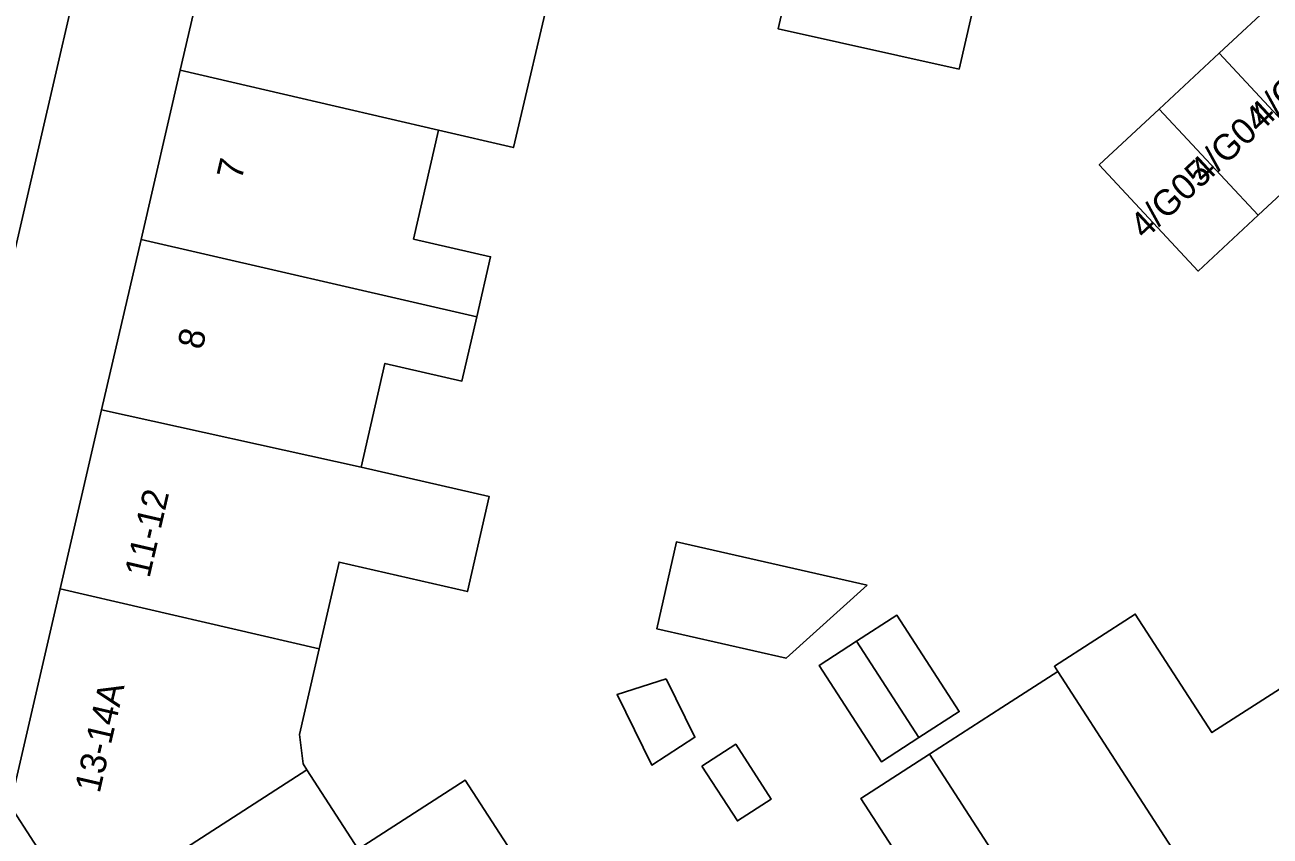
# Model space of a CAD drawing. Extents: x 161801 to 162379, y 382315 to 382832.
# Drawn here: x 161894.26 to 161942.5, y 382605.87 to 382637.32 of the extents above; entities that cross this region are included whole.
import ezdxf

# ---------------------------------------------------------------- set-up
doc = ezdxf.new("R2010")
doc.units = 0
for name, color, linetype in [('IMGEO_Pand', 7, 'Continuous'), ('IMGEO_Pand_nummerreeks', 7, 'Continuous'), ('IMGEO_Rijbaan_lokaal_open', 7, 'Continuous')]:
    doc.layers.add(name, color=color, linetype=linetype)

msp = doc.modelspace()

# ---------------------------------------------------------------- linework, layer by layer
at = {"layer": 'IMGEO_Pand'}
for points in [[(161927.536, 382642.861), (161924.886, 382643.471), (161923.437, 382637.168), (161930.448, 382635.605), (161931.888, 382641.86), (161927.536, 382642.861)], [(161900.274, 382635.56), (161901.764, 382642)], [(161914.727, 382639.11), (161913.18, 382632.56), (161910.284, 382633.233)], [(161940.52, 382636.218), (161942.842, 382638.382)], [(161938.199, 382634.054), (161940.52, 382636.218)], [(161940.52, 382636.218), (161944.36, 382632.099)], [(161898.755, 382628.994), (161900.274, 382635.56)], [(161910.284, 382633.233), (161900.274, 382635.56)], [(161942.038, 382629.935), (161939.717, 382627.771), (161935.877, 382631.89), (161938.199, 382634.054)], [(161942.038, 382629.935), (161938.199, 382634.054)], [(161910.284, 382633.233), (161909.313, 382629.014), (161912.296, 382628.327), (161911.761, 382626)], [(161944.36, 382632.099), (161942.038, 382629.935)], [(161897.228, 382622.395), (161898.755, 382628.994)], [(161911.761, 382626), (161898.755, 382628.994)], [(161911.761, 382626), (161911.187, 382623.507), (161908.202, 382624.194), (161907.278, 382620.174)], [(161895.622, 382615.453), (161897.228, 382622.395)], [(161897.228, 382622.395), (161907.278, 382620.174)], [(161907.278, 382620.174), (161912.245, 382619.032), (161911.397, 382615.348), (161906.428, 382616.491), (161905.656, 382613.133)], [(161926.892, 382615.591), (161923.748, 382612.762), (161918.733, 382613.907), (161919.497, 382617.271), (161926.892, 382615.591)], [(161896.429, 382602.791), (161893.679, 382607.053), (161895.622, 382615.453)], [(161895.622, 382615.453), (161905.656, 382613.133)], [(161928.891, 382609.687), (161930.453, 382610.696), (161928.041, 382614.428), (161926.479, 382613.419)], [(161934.272, 382612.252), (161934.142, 382612.454), (161937.273, 382614.477), (161940.244, 382609.881), (161943.037, 382611.685)], [(161905.656, 382613.133), (161904.891, 382609.807), (161905.03, 382608.666), (161905.177, 382608.439)], [(161926.479, 382613.419), (161925.025, 382612.479), (161927.437, 382608.747), (161928.891, 382609.687)], [(161928.891, 382609.687), (161926.479, 382613.419)], [(161929.306, 382609.044), (161932.103, 382610.851), (161934.272, 382612.252)], [(161934.272, 382612.252), (161942.145, 382600.07)], [(161919.098, 382611.964), (161917.195, 382611.353), (161918.544, 382608.618), (161920.215, 382609.698), (161919.098, 382611.964)], [(161920.488, 382608.58), (161921.86, 382606.456), (161923.169, 382607.302), (161921.797, 382609.425), (161920.488, 382608.58)], [(161927.337, 382601.042), (161927.836, 382601.365), (161929.714, 382602.578), (161926.646, 382607.325), (161929.306, 382609.044)], [(161937.179, 382596.861), (161929.306, 382609.044)], [(161896.429, 382602.791), (161905.177, 382608.439)], [(161905.177, 382608.439), (161907.169, 382605.357), (161911.313, 382608.035), (161913.096, 382605.276)]]:
    msp.add_lwpolyline(points, dxfattribs=at)
at = {"layer": 'IMGEO_Rijbaan_lokaal_open'}
msp.add_lwpolyline([(161898.518, 382648.702), (161892.955, 382624.701)], dxfattribs=at)

# ---------------------------------------------------------------- texts
at = {"layer": 'IMGEO_Pand_nummerreeks'}
for s, rotation, p in [('4/G03', 42.9047, (161942.26, 382633.259)), ('4/G04', 42.9047, (161939.95, 382631.112)), ('7', 76.9739, (161902.648, 382631.269)), ('4/G05', 42.9047, (161937.639, 382628.965)), ('8', 76.9739, (161901.126, 382624.691)), ('11-12', 76.9739, (161899.079, 382615.841)), ('13-14A', 76.976, (161897.148, 382607.497))]:
    msp.add_text(s, height=1, rotation=rotation, dxfattribs=at).set_placement(p)

doc.saveas('drawing.dxf')
